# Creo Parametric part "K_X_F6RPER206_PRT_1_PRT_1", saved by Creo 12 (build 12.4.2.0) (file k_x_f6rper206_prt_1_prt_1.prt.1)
Units: Custom; MM, KILOGRAM, SECS

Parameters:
  PTC_WM_ITERATION = "0"
  PTC_WM_VERSION = "-.0"
  PTC_WM_LIFECYCLE_STATE = "In Work"
  PTC_WM_LIFECYCLE = "MO_CADDocument"
  PTC_WM_CREATED_BY = "Maximilian Roepper (Z0017RMS: MO)"
  PTC_WM_CREATED_ON = "18-Sep-26 11:36:42 AM"
  PTC_WM_MODIFIED_BY = "Maximilian Roepper (Z0017RMS: MO)"
  PTC_WM_MODIFIED_ON = "18-Sep-26 11:36:46 AM"
  PDMLINKNUMBER = "PDM000071455334"
  PTC_WM_NAME = "k_x_f6rper206_prt_1_prt_1.prt"
  PTC_WM_NUMBER = "PDM000071455334"

Other parameters: WEIGHT, WEIGHT_FACTOR, WEIGHT_ADD, _MASS_TEMP, _DIFF_TEMP, MC_ERRORS, SUPPLIER

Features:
  1. coordinate system
  2. datum plane "PRT_YZ"
  3. datum plane "PRT_XY"
  4. datum plane "PRT_XZ"
  5. coordinate system
  6. datum axis
  7. datum axis
  8. datum axis
  9. coordinate system
  10. imported feature
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
Other named items: PRT, SIEMENS_MO, DRW_VIEW_ORG, PRT_X, PRT_Y, PRT_Z, CS0, ROUGH_GROB

Layers: 00_STD_CSYS-KSYS, 01_STD_PLANES-EBENEN, 02_STD_AXES-ACHSEN, 03_STD_CSYS-KSYS, 24_IMPORT_FEAT-IMPORT_KE

Surfaces: 33 tabulated cylinder, 2 plane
